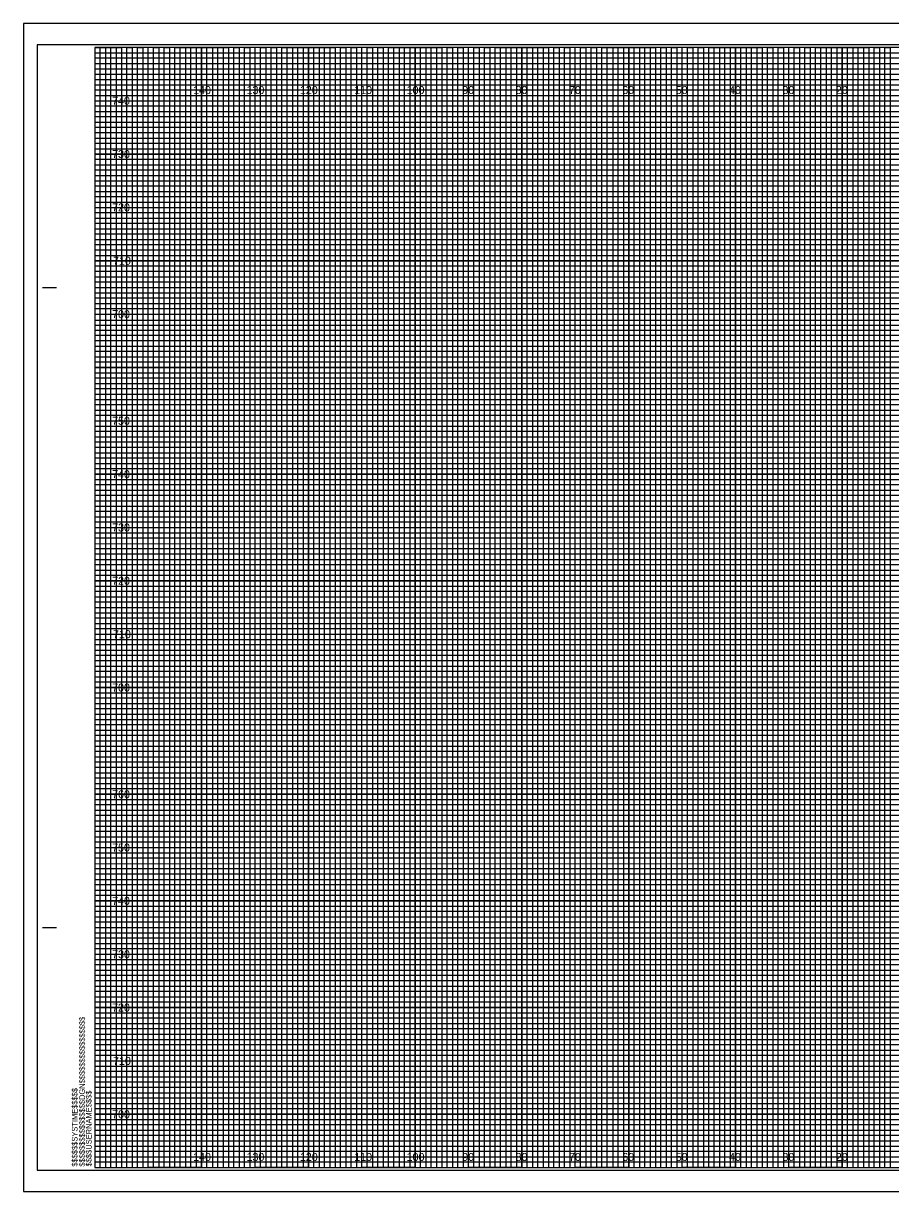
# Model space of a CAD drawing. Extents: x -13 to 323, y -5 to 534.
# Drawn here: x -13.4 to 149.1, y -4.5 to 214.5 of the extents above; entities that cross this region are included whole.
import ezdxf

# ---------------------------------------------------------------- set-up
doc = ezdxf.new("R2010")
doc.units = 0
for name, color, linetype in [('Prop XS Elevation Labels', 7, 'Continuous'), ('Prop XS Offset Labels', 7, 'Continuous'), ('Sheet Cross Section CELL', 7, 'Continuous'), ('Sheet Cross Section Grid Major CELL', 7, 'Continuous'), ('Sheet Cross Section Grid Middle CELL', 7, 'Continuous'), ('Sheet Cross Section Grid Minor 1 CELL', 7, 'Continuous'), ('Sheet Cross Section Grid Minor 2 CELL', 7, 'Continuous'), ('Sheet Cutting Line CELL', 7, 'Continuous'), ('Sheet DOT Grid CELL', 7, 'Continuous'), ('Sheet Plot Border Inside CELL', 7, 'Continuous'), ('Sheet Plot Border Outside CELL', 7, 'Continuous')]:
    doc.layers.add(name, color=color, linetype=linetype)

msp = doc.modelspace()

# ---------------------------------------------------------------- linework, layer by layer
at = {"layer": 'Sheet Cross Section CELL'}
for p, q in [((-9.8, 165), (-7.3, 165)), ((-9.7, 165), (-7.2, 165)), ((-9.8, 45), (-7.3, 45)), ((-9.7, 45), (-7.2, 45))]:
    msp.add_line(p, q, dxfattribs=at)
msp.add_lwpolyline([(320, 210), (0, 210), (0, 0), (320, 0)], close=True, dxfattribs=at)
at = {"layer": 'Sheet Cross Section Grid Major CELL'}
for p, q in [((10, 210), (0, 210)), ((10, 0), (10, 210)), ((30, 210), (20, 210)), ((20, 210), (20, 0)), ((30, 0), (30, 210)), ((50, 210), (40, 210)), ((40, 210), (40, 0)), ((50, 0), (50, 210)), ((70, 210), (60, 210)), ((60, 210), (60, 0)), ((70, 0), (70, 210)), ((90, 210), (80, 210)), ((80, 210), (80, 0)), ((90, 0), (90, 210)), ((110, 210), (100, 210)), ((100, 210), (100, 0)), ((110, 0), (110, 210)), ((130, 210), (120, 210)), ((120, 210), (120, 0)), ((130, 0), (130, 210)), ((150, 210), (140, 210)), ((140, 210), (140, 0)), ((20, 0), (10, 0)), ((40, 0), (30, 0)), ((60, 0), (50, 0)), ((80, 0), (70, 0)), ((100, 0), (90, 0)), ((120, 0), (110, 0)), ((140, 0), (130, 0))]:
    msp.add_line(p, q, dxfattribs=at)
for points in [[(0, 200), (320, 200), (320, 190), (0, 190)], [(0, 180), (320, 180), (320, 170), (0, 170)], [(0, 160), (320, 160), (320, 150), (0, 150)], [(0, 140), (320, 140), (320, 130), (0, 130)], [(0, 120), (320, 120), (320, 110), (0, 110)], [(0, 100), (320, 100), (320, 90), (0, 90)], [(0, 80), (320, 80), (320, 70), (0, 70)], [(0, 60), (320, 60), (320, 50), (0, 50)], [(0, 40), (320, 40), (320, 30), (0, 30)], [(0, 20), (320, 20), (320, 10), (0, 10)]]:
    msp.add_lwpolyline(points, dxfattribs=at)
at = {"layer": 'Sheet Cross Section Grid Middle CELL'}
for points in [[(0, 210), (5, 210), (5, 0), (15, 0), (15, 210), (25, 210), (25, 0), (35, 0), (35, 210), (45, 210), (45, 0), (55, 0), (55, 210), (65, 210), (65, 0), (75, 0), (75, 210), (85, 210), (85, 0), (95, 0), (95, 210), (105, 210), (105, 0), (115, 0), (115, 210), (125, 210), (125, 0), (135, 0), (135, 210), (145, 210), (145, 0), (155, 0)], [(0, 205), (275, 205)], [(0, 185), (320, 185), (320, 195), (0, 195)], [(0, 165), (320, 165), (320, 175), (0, 175)], [(0, 145), (320, 145), (320, 155), (0, 155)], [(0, 125), (320, 125), (320, 135), (0, 135)], [(0, 105), (320, 105), (320, 115), (0, 115)], [(0, 85), (320, 85), (320, 95), (0, 95)], [(0, 65), (320, 65), (320, 75), (0, 75)], [(0, 45), (320, 45), (320, 55), (0, 55)], [(0, 25), (320, 25), (320, 35), (0, 35)], [(0, 5), (320, 5), (320, 15), (0, 15)]]:
    msp.add_lwpolyline(points, dxfattribs=at)
at = {"layer": 'Sheet Cross Section Grid Minor 1 CELL'}
for p, q in [((0, 209), (260, 209)), ((260, 207.98), (0, 207.98)), ((0, 207.98), (0, 207)), ((0, 207), (260, 207)), ((260, 205.89), (0, 205.89)), ((0, 205.89), (0, 204)), ((0, 204), (320, 204))]:
    msp.add_line(p, q, dxfattribs=at)
for points in [[(0, 203), (270, 203), (320, 203), (320, 202), (0, 202)], [(0, 201), (320, 201), (320, 199), (0, 199)], [(0, 198), (320, 198), (320, 197), (0, 196.98)], [(0, 196), (320, 196), (320, 194), (0, 194)], [(0, 193), (320, 193), (320, 192), (0, 192)], [(0, 191), (320, 191), (320, 189), (0, 189)], [(0, 188), (320, 188), (320, 187), (0, 187)], [(0, 186), (320, 186), (320, 184), (0, 184)], [(0, 183), (320, 183), (320, 182), (0, 182)], [(0, 181), (320, 181), (320, 179), (0, 179)], [(0, 178), (320, 178), (320, 177), (0, 177)], [(0, 176), (320, 176), (320, 173.95), (320, 173), (320, 172), (0, 172)], [(0, 174), (320, 174), (320, 173), (0, 173)], [(0, 171), (320, 171), (320, 169), (0, 169.03)], [(0, 169.03), (320, 169), (320, 168), (0, 168)], [(0, 167), (320, 167), (320, 166), (0, 166)], [(0, 164), (320, 164), (320, 163), (0, 163)], [(0, 162), (320, 162), (320, 161), (0, 161)], [(-0.07, 158.89), (320, 158.89), (320, 157.88), (-0.07, 157.88)], [(0, 157), (320, 157), (320, 156), (0, 156)], [(0, 154), (320, 154), (320, 153), (0, 153)], [(0, 152), (320, 152), (320, 151), (0, 151)], [(0, 149), (320, 149), (320, 148), (0, 148)], [(0, 147), (320, 147), (320, 146), (0, 146)], [(0, 144), (320, 144), (320, 143), (0, 143)], [(0, 142), (320, 142), (320, 141), (0, 141)], [(0, 139), (320, 139), (319.99, 137.98), (0, 138)], [(0, 137), (320, 137), (320, 136), (0, 136)], [(0, 134), (320, 134), (320, 133), (0, 133)], [(0, 132), (320, 132), (320, 131), (0, 131)], [(0, 129), (320, 129), (320, 128), (0, 128)], [(0, 127), (320, 127), (320, 126), (0, 126)], [(0, 124), (320, 124), (320, 123), (0, 123)], [(0, 122), (320, 122), (320, 121), (0, 121)], [(0, 119), (320, 119), (320, 118), (0, 118)], [(0, 116.99), (320.07, 116.91), (320, 116), (0, 116)], [(0, 114), (320, 114), (320, 113), (0, 113)], [(0, 112), (320, 112), (320, 111), (0, 111)], [(0, 109), (320, 109), (320, 108), (0, 108)], [(0, 107), (320, 107), (320, 106), (0, 106)], [(0, 104), (320, 104), (320, 103), (0, 103)], [(0, 102), (320, 102), (320, 101), (0, 101)], [(0, 99), (320, 99), (320, 98), (0, 98)], [(0, 97), (320, 97), (320, 96), (0, 96)], [(0, 94), (320, 94), (320, 93), (0, 93)], [(0, 92), (320, 92), (320, 91), (0, 91)], [(0, 89), (320, 89), (320, 88), (0, 88)], [(0, 87), (320, 87), (320, 86), (0, 86)], [(0, 84), (320, 84), (320, 83), (0, 83)], [(0, 82), (320, 82), (320, 81), (0, 81)], [(0, 79), (320, 79), (319.99, 77.98), (0, 78)], [(0, 77), (320, 77), (320, 76), (0, 76)], [(0, 74), (320, 74), (320, 73), (0, 73)], [(0, 72), (320, 72), (320, 71), (0, 71)], [(0, 69), (320, 69), (320, 68), (0, 68)], [(0, 67), (320, 67), (320, 66), (0, 66)], [(0, 64), (320, 64), (320, 63), (0, 63)], [(0, 62), (320, 62), (320, 61), (0, 61)], [(0, 59), (320, 59), (320, 58), (0, 58)], [(0, 56.99), (320.07, 56.91), (320, 56), (0, 56)], [(0, 54), (320, 54), (320, 53), (0, 53)], [(0, 52), (320, 52), (320, 51), (0, 51)], [(0, 49), (320, 49), (320, 48), (0, 48)], [(0, 47), (320, 47), (320, 46), (0, 46)], [(0, 44), (320, 44), (320, 43), (0, 43)], [(0, 42), (320, 42), (320, 41), (0, 41)], [(0, 39), (320, 39), (320, 38), (0, 38)], [(0, 37), (320, 37), (320, 36), (0, 36)], [(0, 34), (320, 34), (320, 33), (0, 33)], [(0, 32), (320, 32), (320, 31), (0, 31)], [(0, 29), (320, 29), (320, 28), (0, 28)], [(0, 27), (320, 27), (320, 26), (0, 26)], [(0, 24), (320, 24), (320, 23), (0, 23)], [(0, 22), (320, 22), (320, 21), (0, 21)], [(0, 19), (320, 19), (320, 18), (0, 18)], [(0, 17), (320, 17), (320, 16), (0, 16)], [(0, 14), (320, 14), (320, 13), (0, 13)], [(0, 12), (320, 12), (320, 11), (0, 11)], [(0, 9), (320, 9), (320, 8), (0, 8)], [(0, 7), (320, 7), (320, 6), (0, 6)], [(0, 4), (320, 4), (320, 3), (0, 3)], [(0, 2), (320, 2), (320, 1), (0, 1)]]:
    msp.add_lwpolyline(points, dxfattribs=at)
at = {"layer": 'Sheet Cross Section Grid Minor 2 CELL'}
for points in [[(0, 0), (1, 0), (1, 210), (2, 210), (2, 0)], [(2, 0), (3, 0), (3, 210), (4, 210), (4, 0)], [(5, 0), (6, 0), (6, 210), (7, 210), (7, 0)], [(7, 0), (8, 0), (8, 210), (9, 210), (9, 0)], [(10, 0), (11, 0), (11, 210), (12, 210), (12, 0)], [(12, 0), (13, 0), (13, 210), (14, 210), (14, 0)], [(15, 0), (16, 0), (16, 210), (17, 210), (17, 0)], [(17, 0), (18, 0), (18, 210), (19, 210), (19, 0)], [(20, 0), (21, 0), (21, 210), (22, 210), (22, 0)], [(22, 0), (23, 0), (23, 210), (24, 210), (24, 0)], [(25, 0), (26, 0), (26, 210), (27, 210), (27, 0)], [(27, 0), (28, 0), (28, 210), (29, 210), (29, 0)], [(30, 0), (31, 0), (31, 210), (32, 210), (32, 0)], [(32, 0), (33, 0), (33, 210), (34, 210), (34, 0)], [(35, 0), (36, 0), (36, 210), (37, 210), (37, 0)], [(37, 0), (38, 0), (38, 210), (39, 210), (39, 0)], [(40, 0), (41, 0), (41, 210), (42, 210), (42, 0)], [(42, 0), (43, 0), (43, 210), (44, 210), (44, 0)], [(45, 0), (46, 0), (46, 210), (47, 210), (47, 0)], [(47, 0), (48, 0), (48, 210), (49, 210), (49, 0)], [(50, 0), (51, 0), (51, 210), (52, 210), (52, 0)], [(52, 0), (53, 0), (53, 210), (54, 210), (54, 0)], [(55, 0), (56, 0), (56, 210), (57, 210), (57, 0)], [(57, 0), (58, 0), (58, 210), (59, 210), (59, 0)], [(60, 0), (61, 0), (61, 210), (62, 210), (62, 0)], [(62, 0), (63, 0), (63, 210), (64, 210), (64, 0)], [(65, 0), (66, 0), (66, 210), (67, 210), (67, 0)], [(67, 0), (68, 0), (68, 210), (69, 210), (69, 0)], [(70, 0), (71, 0), (71, 210), (72, 210), (72, 0)], [(72, 0), (73, 0), (73, 210), (74, 210), (74, 0)], [(75, 0), (76, 0), (76, 210), (77, 210), (77, 0)], [(77, 0), (78, 0), (78, 210), (79, 210), (79, 0)], [(80, 0), (81, 0), (81, 210), (82, 210), (82, 0)], [(82, 0), (83, 0), (83, 210), (84, 210), (84, 0)], [(85, 0), (86, 0), (86, 210), (87, 210), (87, 0)], [(87, 0), (88, 0), (88, 210), (89, 210), (89, 0)], [(90, 0), (91, 0), (91, 210), (92, 210), (92, 0)], [(92, 0), (93, 0), (93, 210), (94, 210), (94, 0)], [(95, 0), (96, 0), (96, 210), (97, 210), (97, 0)], [(97, 0), (98, 0), (98, 210), (99, 210), (99, 0)], [(100, 0), (101, 0), (101, 210), (102, 210), (102, 0)], [(102, 0), (103, 0), (103, 210), (104, 210), (104, 0)], [(105, 0), (106, 0), (106, 210), (107, 210), (107, 0)], [(107, 0), (108, 0), (108, 210), (109, 210), (109, 0)], [(110, 0), (111, 0), (111, 210), (112, 210), (112, 0)], [(112, 0), (113, 0), (113, 210), (114, 210), (114, 0)], [(115, 0), (116, 0), (116, 210), (117, 210), (117, 0)], [(117, 0), (118, 0), (118, 210), (119, 210), (119, 0)], [(120, 0), (121, 0), (121, 210), (122, 210), (122, 0)], [(122, 0), (123, 0), (123, 210), (124, 210), (124, 0)], [(125, 0), (126, 0), (126, 210), (127, 210), (127, 0)], [(127, 0), (128, 0), (128, 210), (129, 210), (129, 0)], [(130, 0), (131, 0), (131, 210), (132, 210), (132, 0)], [(132, 0), (133, 0), (133, 210), (134, 210), (134, 0)], [(135, 0), (136, 0), (136, 210), (137, 210), (137, 0)], [(137, 0), (138, 0), (138, 210), (139, 210), (139, 0)], [(140, 0), (141, 0), (141, 210), (142, 210), (142, 0)], [(142, 0), (143, 0), (143, 210), (144, 210), (144, 0)], [(145, 0), (146, 0), (146, 210), (147, 210), (147, 0)], [(147, 0), (148, 0), (148, 210), (149, 210), (149, 0)]]:
    msp.add_lwpolyline(points, dxfattribs=at)
at = {"layer": 'Sheet Cutting Line CELL'}
for p, q in [((323.3, 214.5), (-13.4, 214.5)), ((-13.4, 214.5), (-13.4, -4.5)), ((-13.4, -4.5), (323.3, -4.5))]:
    msp.add_line(p, q, dxfattribs=at)
at = {"layer": 'Sheet DOT Grid CELL'}
for p, q in [((10, 0), (10, 210)), ((20, 0), (20, 210)), ((30, 0), (30, 210)), ((40, 0), (40, 210)), ((50, 0), (50, 210)), ((60, 0), (60, 210)), ((70, 0), (70, 210)), ((80, 0), (80, 210)), ((90, 0), (90, 210)), ((100, 0), (100, 210)), ((110, 0), (110, 210)), ((120, 0), (120, 210)), ((130, 0), (130, 210)), ((140, 0), (140, 210)), ((0, 200), (320, 200)), ((0, 190), (320, 190)), ((0, 180), (320, 180)), ((0, 170), (320, 170)), ((0, 160), (320, 160)), ((0, 150), (320, 150)), ((0, 140), (320, 140)), ((0, 130), (320, 130)), ((0, 120), (320, 120)), ((0, 110), (320, 110)), ((0, 100), (320, 100)), ((0, 90), (320, 90)), ((0, 80), (320, 80)), ((0, 70), (320, 70)), ((0, 60), (320, 60)), ((0, 50), (320, 50)), ((0, 40), (320, 40)), ((0, 30), (320, 30)), ((0, 20), (320, 20)), ((0, 10), (320, 10))]:
    msp.add_line(p, q, dxfattribs=at)
at = {"layer": 'Sheet Plot Border Inside CELL'}
msp.add_lwpolyline([(-10.8, -0.5), (322.4, -0.5), (322.4, 210.5), (-10.8, 210.5)], close=True, dxfattribs=at)
at = {"layer": 'Sheet Plot Border Outside CELL'}
msp.add_lwpolyline([(-13.4, -4.5), (323.3, -4.5), (323.3, 214.5), (-13.4, 214.5)], close=True, dxfattribs=at)

# ---------------------------------------------------------------- texts
at = {"layer": 'Prop XS Elevation Labels'}
for s, p in [('740', (3.22, 199.25)), ('730', (3.22, 189.25)), ('720', (3.22, 179.25)), ('710', (3.4, 169.25)), ('700', (3.22, 159.25)), ('750', (3.22, 139.25)), ('740', (3.22, 129.25)), ('730', (3.22, 119.25)), ('720', (3.22, 109.25)), ('710', (3.4, 99.25)), ('700', (3.22, 89.25)), ('760', (3.22, 69.25)), ('750', (3.22, 59.25)), ('740', (3.22, 49.25)), ('730', (3.22, 39.25)), ('720', (3.22, 29.25)), ('710', (3.4, 19.25)), ('700', (3.22, 9.25))]:
    msp.add_text(s, height=1.5, dxfattribs=at).set_placement(p)
at = {"layer": 'Prop XS Offset Labels'}
for s, p in [('140', (18.4, 201.25)), ('130', (28.4, 201.25)), ('120', (38.4, 201.25)), ('110', (48.58, 201.25)), ('100', (58.4, 201.25)), ('90', (68.81, 201.25)), ('80', (78.81, 201.25)), ('70', (88.81, 201.25)), ('60', (98.81, 201.25)), ('50', (108.81, 201.25)), ('40', (118.81, 201.25)), ('30', (128.81, 201.25)), ('20', (138.81, 201.25)), ('140', (18.4, 1.25)), ('130', (28.4, 1.25)), ('120', (38.4, 1.25)), ('110', (48.58, 1.25)), ('100', (58.4, 1.25)), ('90', (68.81, 1.25)), ('80', (78.81, 1.25)), ('70', (88.81, 1.25)), ('60', (98.81, 1.25)), ('50', (108.81, 1.25)), ('40', (118.81, 1.25)), ('30', (128.81, 1.25)), ('20', (138.81, 1.25))]:
    msp.add_text(s, height=1.5, dxfattribs=at).set_placement(p)
at = {"layer": 'Sheet Cross Section CELL'}
for s, p in [('$$$$$$$$$$$$$$$$DGN$$$$$$$$$$$$$$$$', (-1.88, 0.18)), ('$$$$$$SYSTIME$$$$$', (-3.26, 0.18)), ('$$$$USERNAME$$$$', (-0.62, 0.23))]:
    msp.add_text(s, height=1.05, rotation=90, dxfattribs=at).set_placement(p)

doc.saveas('drawing.dxf')
